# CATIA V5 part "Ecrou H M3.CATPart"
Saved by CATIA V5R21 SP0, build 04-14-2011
Part number: Ecrou H M3
Material "Acier": density 7860 kg/m3, Young's modulus 2e+11 Pa, Poisson ratio 0.266, thermal expansion 1.17e-05 1/K
Bounding box of the stored display mesh (mm): x -2.5 to 2.5, y -2.887 to 2.887, z 0 to 2
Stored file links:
  C:\Users\Olivier\Desktop\redaction CATIA (local)\CATIA\DONNEES\Exercice assemblage 1 (chassis et socle)\Assemblage chassis et socle (Product inclus)\Ecrou H M3.CATPart
  C:\Program Files\Dassault Systemes\B21\win_b64\startup\materials\French\Catalog.CATMaterial
  C:\Users\Olivier\Desktop\redaction CATIA (local)\CATIA\DONNEES\Exercice assemblage 1 (chassis et socle)\Assemblage chassis et socle (Product inclus)\CATIA_EnvironmentMap_Satin_512x512.jpg
  C:\Users\Olivier\Desktop\redaction CATIA (local)\pompe à moteur de ventilation refait\Pompe_a_moteur_de_ventilation.CATProduct
  C:\Users\Olivier\Desktop\redaction CATIA (local)\pompe à moteur de ventilation refait\Ecrou a collerette M5.CATPart
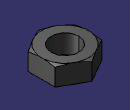
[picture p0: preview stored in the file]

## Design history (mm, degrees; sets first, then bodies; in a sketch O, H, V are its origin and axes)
Body1 (main body), material "Acier"
  Sketch1 on xy-plane, origin (0, 0, 0), H (1, 0, 0), V (0, 1, 0)
    circle A1 centre (0, 0) radius 1.5
    point P1 (2.5, -1.4434)
    point P2 (2.5, 1.4434)
    point P3 (0, 2.8868)
    point P4 (-2.5, 1.4434)
    point P5 (-2.5, -1.4434)
    point P6 (0, -2.8868)
    point P7 (2.5, 0)
    line L1 (2.5, -1.4434) -> (2.5, 1.4434)
    line L2 (2.5, 1.4434) -> (0, 2.8868)
    line L3 (0, 2.8868) -> (-2.5, 1.4434)
    line L4 (-2.5, 1.4434) -> (-2.5, -1.4434)
    line L5 (-2.5, -1.4434) -> (0, -2.8868)
    line L6 (0, -2.8868) -> (2.5, -1.4434)
    construction line L7 (0, 0) -> (2.5, 0)
    construction circle A2 centre (0, 0) radius 2.8868
    construction arc A3 centre (-2.5, -1.4434) radius 2.8868 from (-2.5, 1.4434) to (0, -2.8868) cw
    construction arc A4 centre (2.5, 1.4434) radius 2.8868 from (0, 2.8868) to (2.5, -1.4434) ccw
    distance L1 L4 = 5
    horizontal: L7 H
    coincidence: A2 P1, A2 P2, A2 P3, A2 P4, A2 P5, A2 P6, A3 O, A4 O
    midpoint: P7 L1
  Pad1: profile Sketch1, direction (0, 0, 1), length 2
  Sketch2 on yz-plane, origin (0, 0, 0), H (0, 1, 0), V (0, 0, 1)
    line L1 (2.4595, 2.0276) -> (2.9071, 2.0276)
    point P1 (2.4595, 2.0276)
    line L2 (2.9071, 2.0276) -> (2.9071, 1.8177)
    line L3 (2.9071, 1.8177) -> (2.4663, 2.0244)
    horizontal: L1 H
    vertical: L2 V
    coincidence: L3 P1
  Groove1: profile Sketch2, axis Sketch2.V, angle 360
